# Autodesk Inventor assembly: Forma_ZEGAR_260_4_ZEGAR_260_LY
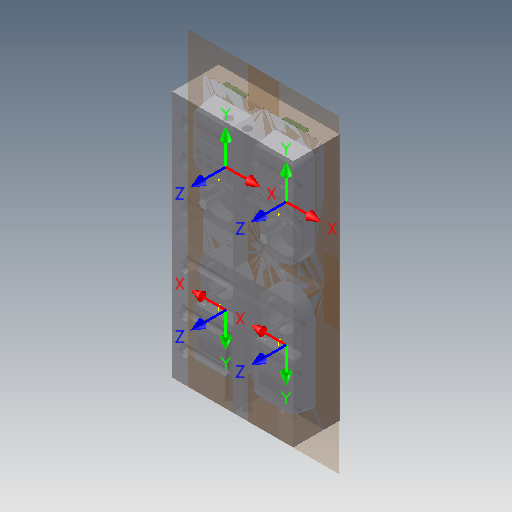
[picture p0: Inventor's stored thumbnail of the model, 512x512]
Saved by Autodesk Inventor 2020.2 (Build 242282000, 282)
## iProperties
Created: 2015-01
Part Number: Forma_ZEGAR_260_4_ZEGAR_260_LY
Document SubType Name: Assembly
Designer: F.Stasiak
Catalog Web Link: www.expertbooks.pl
Manager: www.cadconsulting.pl
Company: Fabian Stasiak CAD Consulting
Author: F.Stasiak
Subject: Zbiór ćwiczeń. Autodesk Inventor 2020. Kurs Professional
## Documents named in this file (10)
- C:\2020_Kurs_Professional\R6 Formy\Komponenty\Forma_ZEGAR_260_4_ZEGAR_260_LY.iam
- C:\2020_Kurs_Professional\R6 Formy\Komponenty\Forma_ZEGAR_260_4_ZEGAR_260_PZ.iam
- C:\2020_Kurs_Professional\R6 Formy\Komponenty\Forma_ZEGAR_260_4_ZEGAR_260_CV_2.ipt
- C:\2020_Kurs_Professional\R6 Formy\Komponenty\Forma_ZEGAR_260_4_ZEGAR_260_CV_3.ipt
- C:\2020_Kurs_Professional\R6 Formy\Komponenty\Forma_ZEGAR_260_4_ZEGAR_260_CV_4.ipt
- C:\2020_Kurs_Professional\R6 Formy\Komponenty\Forma_ZEGAR_260_4_ZEGAR_260_CV_1.ipt
- C:\2020_Kurs_Professional\R6 Formy\Komponenty\Forma_ZEGAR_260_4_ZEGAR_260_CR_2.ipt
- C:\2020_Kurs_Professional\R6 Formy\Komponenty\Forma_ZEGAR_260_4_ZEGAR_260_CR_3.ipt
- C:\2020_Kurs_Professional\R6 Formy\Komponenty\Forma_ZEGAR_260_4_ZEGAR_260_CR_4.ipt
- C:\2020_Kurs_Professional\R6 Formy\Komponenty\Forma_ZEGAR_260_4_ZEGAR_260_CR_1.ipt
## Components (12 placed, 9 different names)
1. Forma_ZEGAR_260_4_ZEGAR_260_PZ:1 [sub-assembly] — Równoległy:1, Równoległy:2, Równoległy:3, Równoległy:13, Równoległy:14, Równoległy:15, Równoległy:25, Równoległy:26, Równoległy:27, Równoległy:37, Równoległy:38, Równoległy:39
2. Forma_ZEGAR_260_4_ZEGAR_260_PZ:2 [sub-assembly] — Równoległy:4, Równoległy:5, Równoległy:6, Równoległy:16, Równoległy:17, Równoległy:18, Równoległy:28, Równoległy:29, Równoległy:30, Równoległy:40, Równoległy:41, Równoległy:42
3. Forma_ZEGAR_260_4_ZEGAR_260_PZ:3 [sub-assembly] — Równoległy:7, Równoległy:8, Równoległy:9, Równoległy:19, Równoległy:20, Równoległy:21, Równoległy:31, Równoległy:32, Równoległy:33, Równoległy:43, Równoległy:44, Równoległy:45
4. Forma_ZEGAR_260_4_ZEGAR_260_PZ:4 [sub-assembly] — Równoległy:10, Równoległy:11, Równoległy:12, Równoległy:22, Równoległy:23, Równoległy:24, Równoległy:34, Równoległy:35, Równoległy:36, Równoległy:46, Równoległy:47, Równoległy:48
5. Forma_ZEGAR_260_4_ZEGAR_260_CV_1:1 — Równoległy:13, Równoległy:14, Równoległy:15
6. Forma_ZEGAR_260_4_ZEGAR_260_CV_2:1 — Równoległy:16, Równoległy:17, Równoległy:18
7. Forma_ZEGAR_260_4_ZEGAR_260_CV_3:1 — Równoległy:19, Równoległy:20, Równoległy:21
8. Forma_ZEGAR_260_4_ZEGAR_260_CV_4:1 — Równoległy:22, Równoległy:23, Równoległy:24
9. Forma_ZEGAR_260_4_ZEGAR_260_CR_1:1 — Równoległy:25, Równoległy:26, Równoległy:27, Równoległy:37, Równoległy:38, Równoległy:39
10. Forma_ZEGAR_260_4_ZEGAR_260_CR_2:1 — Równoległy:28, Równoległy:29, Równoległy:30, Równoległy:40, Równoległy:41, Równoległy:42
11. Forma_ZEGAR_260_4_ZEGAR_260_CR_3:1 — Równoległy:31, Równoległy:32, Równoległy:33, Równoległy:43, Równoległy:44, Równoległy:45
12. Forma_ZEGAR_260_4_ZEGAR_260_CR_4:1 — Równoległy:34, Równoległy:35, Równoległy:36, Równoległy:46, Równoległy:47, Równoległy:48
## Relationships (48: Flush 48)
- Równoległy:1 [Flush]: Forma_ZEGAR_260_4_ZEGAR_260_PZ:1
- Równoległy:2 [Flush]: Forma_ZEGAR_260_4_ZEGAR_260_PZ:1
- Równoległy:3 [Flush]: Forma_ZEGAR_260_4_ZEGAR_260_PZ:1
- Równoległy:4 [Flush]: Forma_ZEGAR_260_4_ZEGAR_260_PZ:2
- Równoległy:5 [Flush]: Forma_ZEGAR_260_4_ZEGAR_260_PZ:2
- Równoległy:6 [Flush]: Forma_ZEGAR_260_4_ZEGAR_260_PZ:2
- Równoległy:7 [Flush]: Forma_ZEGAR_260_4_ZEGAR_260_PZ:3
- Równoległy:8 [Flush]: Forma_ZEGAR_260_4_ZEGAR_260_PZ:3
- Równoległy:9 [Flush]: Forma_ZEGAR_260_4_ZEGAR_260_PZ:3
- Równoległy:10 [Flush]: Forma_ZEGAR_260_4_ZEGAR_260_PZ:4
- Równoległy:11 [Flush]: Forma_ZEGAR_260_4_ZEGAR_260_PZ:4
- Równoległy:12 [Flush]: Forma_ZEGAR_260_4_ZEGAR_260_PZ:4
- Równoległy:13 [Flush]: Forma_ZEGAR_260_4_ZEGAR_260_PZ:1 ↔ Forma_ZEGAR_260_4_ZEGAR_260_CV_1:1
- Równoległy:14 [Flush]: Forma_ZEGAR_260_4_ZEGAR_260_PZ:1 ↔ Forma_ZEGAR_260_4_ZEGAR_260_CV_1:1
- Równoległy:15 [Flush]: Forma_ZEGAR_260_4_ZEGAR_260_PZ:1 ↔ Forma_ZEGAR_260_4_ZEGAR_260_CV_1:1
- Równoległy:16 [Flush]: Forma_ZEGAR_260_4_ZEGAR_260_PZ:2 ↔ Forma_ZEGAR_260_4_ZEGAR_260_CV_2:1
- Równoległy:17 [Flush]: Forma_ZEGAR_260_4_ZEGAR_260_PZ:2 ↔ Forma_ZEGAR_260_4_ZEGAR_260_CV_2:1
- Równoległy:18 [Flush]: Forma_ZEGAR_260_4_ZEGAR_260_PZ:2 ↔ Forma_ZEGAR_260_4_ZEGAR_260_CV_2:1
- Równoległy:19 [Flush]: Forma_ZEGAR_260_4_ZEGAR_260_PZ:3 ↔ Forma_ZEGAR_260_4_ZEGAR_260_CV_3:1
- Równoległy:20 [Flush]: Forma_ZEGAR_260_4_ZEGAR_260_PZ:3 ↔ Forma_ZEGAR_260_4_ZEGAR_260_CV_3:1
- Równoległy:21 [Flush]: Forma_ZEGAR_260_4_ZEGAR_260_PZ:3 ↔ Forma_ZEGAR_260_4_ZEGAR_260_CV_3:1
- Równoległy:22 [Flush]: Forma_ZEGAR_260_4_ZEGAR_260_PZ:4 ↔ Forma_ZEGAR_260_4_ZEGAR_260_CV_4:1
- Równoległy:23 [Flush]: Forma_ZEGAR_260_4_ZEGAR_260_PZ:4 ↔ Forma_ZEGAR_260_4_ZEGAR_260_CV_4:1
- Równoległy:24 [Flush]: Forma_ZEGAR_260_4_ZEGAR_260_PZ:4 ↔ Forma_ZEGAR_260_4_ZEGAR_260_CV_4:1
- Równoległy:25 [Flush]: Forma_ZEGAR_260_4_ZEGAR_260_PZ:1 ↔ Forma_ZEGAR_260_4_ZEGAR_260_CR_1:1
- Równoległy:26 [Flush]: Forma_ZEGAR_260_4_ZEGAR_260_PZ:1 ↔ Forma_ZEGAR_260_4_ZEGAR_260_CR_1:1
- Równoległy:27 [Flush]: Forma_ZEGAR_260_4_ZEGAR_260_PZ:1 ↔ Forma_ZEGAR_260_4_ZEGAR_260_CR_1:1
- Równoległy:28 [Flush]: Forma_ZEGAR_260_4_ZEGAR_260_PZ:2 ↔ Forma_ZEGAR_260_4_ZEGAR_260_CR_2:1
- Równoległy:29 [Flush]: Forma_ZEGAR_260_4_ZEGAR_260_PZ:2 ↔ Forma_ZEGAR_260_4_ZEGAR_260_CR_2:1
- Równoległy:30 [Flush]: Forma_ZEGAR_260_4_ZEGAR_260_PZ:2 ↔ Forma_ZEGAR_260_4_ZEGAR_260_CR_2:1
- Równoległy:31 [Flush]: Forma_ZEGAR_260_4_ZEGAR_260_PZ:3 ↔ Forma_ZEGAR_260_4_ZEGAR_260_CR_3:1
- Równoległy:32 [Flush]: Forma_ZEGAR_260_4_ZEGAR_260_PZ:3 ↔ Forma_ZEGAR_260_4_ZEGAR_260_CR_3:1
- Równoległy:33 [Flush]: Forma_ZEGAR_260_4_ZEGAR_260_PZ:3 ↔ Forma_ZEGAR_260_4_ZEGAR_260_CR_3:1
- Równoległy:34 [Flush]: Forma_ZEGAR_260_4_ZEGAR_260_PZ:4 ↔ Forma_ZEGAR_260_4_ZEGAR_260_CR_4:1
- Równoległy:35 [Flush]: Forma_ZEGAR_260_4_ZEGAR_260_PZ:4 ↔ Forma_ZEGAR_260_4_ZEGAR_260_CR_4:1
- Równoległy:36 [Flush]: Forma_ZEGAR_260_4_ZEGAR_260_PZ:4 ↔ Forma_ZEGAR_260_4_ZEGAR_260_CR_4:1
- Równoległy:37 [Flush]: Forma_ZEGAR_260_4_ZEGAR_260_PZ:1 ↔ Forma_ZEGAR_260_4_ZEGAR_260_CR_1:1
- Równoległy:38 [Flush]: Forma_ZEGAR_260_4_ZEGAR_260_PZ:1 ↔ Forma_ZEGAR_260_4_ZEGAR_260_CR_1:1
- Równoległy:39 [Flush]: Forma_ZEGAR_260_4_ZEGAR_260_PZ:1 ↔ Forma_ZEGAR_260_4_ZEGAR_260_CR_1:1
- Równoległy:40 [Flush]: Forma_ZEGAR_260_4_ZEGAR_260_PZ:2 ↔ Forma_ZEGAR_260_4_ZEGAR_260_CR_2:1
- Równoległy:41 [Flush]: Forma_ZEGAR_260_4_ZEGAR_260_PZ:2 ↔ Forma_ZEGAR_260_4_ZEGAR_260_CR_2:1
- Równoległy:42 [Flush]: Forma_ZEGAR_260_4_ZEGAR_260_PZ:2 ↔ Forma_ZEGAR_260_4_ZEGAR_260_CR_2:1
- Równoległy:43 [Flush]: Forma_ZEGAR_260_4_ZEGAR_260_PZ:3 ↔ Forma_ZEGAR_260_4_ZEGAR_260_CR_3:1
- Równoległy:44 [Flush]: Forma_ZEGAR_260_4_ZEGAR_260_PZ:3 ↔ Forma_ZEGAR_260_4_ZEGAR_260_CR_3:1
- Równoległy:45 [Flush]: Forma_ZEGAR_260_4_ZEGAR_260_PZ:3 ↔ Forma_ZEGAR_260_4_ZEGAR_260_CR_3:1
- Równoległy:46 [Flush]: Forma_ZEGAR_260_4_ZEGAR_260_PZ:4 ↔ Forma_ZEGAR_260_4_ZEGAR_260_CR_4:1
- Równoległy:47 [Flush]: Forma_ZEGAR_260_4_ZEGAR_260_PZ:4 ↔ Forma_ZEGAR_260_4_ZEGAR_260_CR_4:1
- Równoległy:48 [Flush]: Forma_ZEGAR_260_4_ZEGAR_260_PZ:4 ↔ Forma_ZEGAR_260_4_ZEGAR_260_CR_4:1
